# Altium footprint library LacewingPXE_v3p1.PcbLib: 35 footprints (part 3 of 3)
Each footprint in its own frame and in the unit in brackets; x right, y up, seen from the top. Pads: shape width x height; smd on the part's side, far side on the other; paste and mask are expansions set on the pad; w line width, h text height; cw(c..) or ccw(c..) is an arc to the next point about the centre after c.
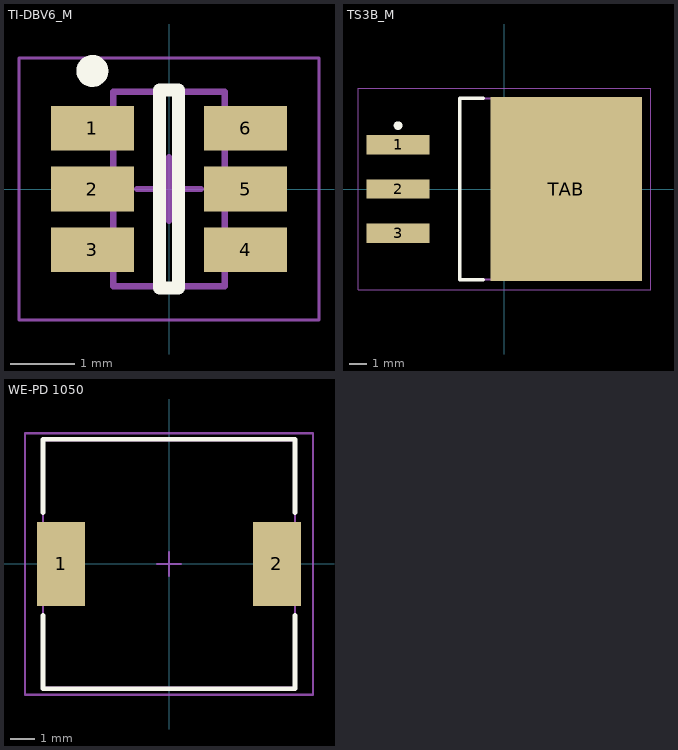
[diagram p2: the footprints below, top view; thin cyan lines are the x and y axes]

## TI-DBV6_M [mm] "SOT-23, 6-Leads, Body 2.90x1.60mm, Pitch 0.95mm, IPC Low Density"
height 1.45
pads (6):
  rect 1.3x0.7 smd: 1(-1.2,0.95) 2(-1.2,0) 3(-1.2,-0.95) 4(1.2,-0.95) 5(1.2,0) 6(1.2,0.95)
Top Overlay:
  circle w0.25: c-1.2,1.85 r0.125
  lines w0.2: -0.15,-1.55 0.15,-1.55 0.15,1.55 -0.15,1.55 -0.15,-1.55
Mechanical 13:
  lines w0.1: -0.875,-1.525 -0.875,1.525 0.875,1.525 0.875,-1.525 -0.875,-1.525
Mechanical 15:
  lines w0.05: -2.35,-2.05 -2.35,2.05 2.35,2.05 2.35,-2.05 -2.35,-2.05
  lines w0.1: -0.5,0 0.5,0 ; 0,-0.5 0,0.5
3D body: height 1.45, standoff 0, extent -0.875,-1.525 0.875,1.525

## TS3B_M [mm] "D2-PAK, 4-Leads, Body 8.6x10.2mm, Pitch 2.54mm, Lead Span 14.2mm, IPC Low Density"
height 4.64
pads (4):
  rect 3.6x1.1 smd: 1(-6.1,2.54) 2(-6.1,0) 3(-6.1,-2.54)
  rect 8.7x10.55 smd: TAB(3.55,0)
Top Overlay:
  circle w0.25: c-6.1,3.64 r0.125
  lines w0.2: -1.2,-5.2 -2.55,-5.2 -2.55,5.2 -1.2,5.2
Mechanical 13:
  lines w0.1: -2.55,-5.2 6.34,-5.2 6.34,5.2 -2.55,5.2 -2.55,-5.2
Mechanical 15:
  lines w0.05: -8.4,-5.775 8.4,-5.775 8.4,5.775 -8.4,5.775 -8.4,-5.775
  lines w0.1: -0.5,0 0.5,0 ; 0,-0.5 0,0.5
3D body: height 4.64, standoff 0, extent -2.55,-5.2 6.34,5.2

## WE-PD 1050 [mm] "SMD Inductor, 2-Leads, Body 10,0x10,0mm"
height 5
pads (2):
  rect 2x3.5 smd: 1(-4.5,0) 2(4.5,0)
Top Overlay:
  lines w0.2: -5.25,-2.15 -5.25,-5.2 5.25,-5.2 5.25,-2.15 ; -5.25,2.15 -5.25,5.2 5.25,5.2 5.25,2.15
Mechanical 13:
  lines w0.1: -5.25,-5.15 -5.25,5.15 5.25,5.15 5.25,-5.15 -5.25,-5.15
Mechanical 15:
  lines w0.1: -0.5,0 0.5,0 ; 0,-0.5 0,0.5 ; -6,-5.45 -6,5.45 6,5.45 6,-5.45 -6,-5.45
3D body "7447714xx.stp": height 4.75, standoff -0.05, extent -5,-5 5,5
